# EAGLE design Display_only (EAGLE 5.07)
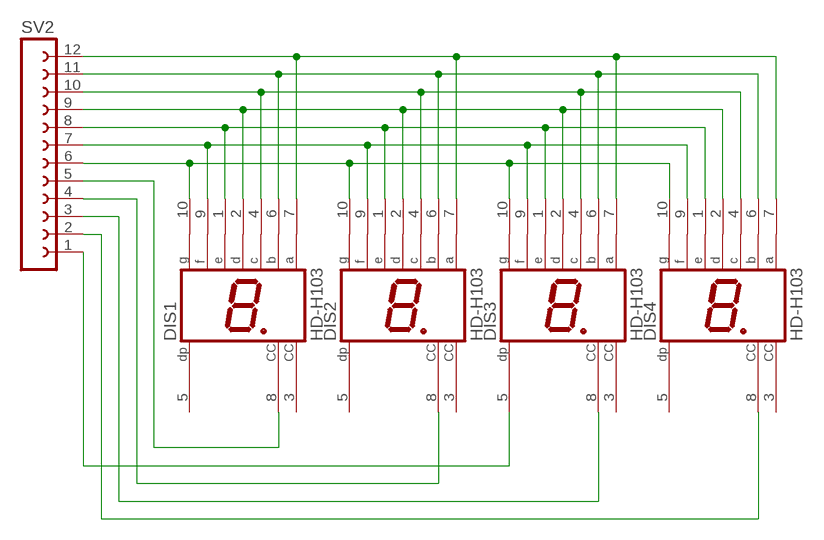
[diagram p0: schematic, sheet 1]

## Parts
DIS1  HD-H103  [HDSP-M]
DIS2  HD-H103  [HDSP-M]
DIS3  HD-H103  [HDSP-M]
DIS4  HD-H103  [HDSP-M]
SV2  FE12-1  [FE12]

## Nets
N$16: DIS1.9(F) DIS2.9(F) DIS3.9(F) DIS4.9(F) SV2.7
N$17: DIS1.7(A) DIS2.7(A) DIS3.7(A) DIS4.7(A) SV2.12
N$18: DIS1.6(B) DIS2.6(B) DIS3.6(B) DIS4.6(B) SV2.11
N$19: DIS1.4(C) DIS2.4(C) DIS3.4(C) DIS4.4(C) SV2.10
N$20: DIS1.2(D) DIS2.2(D) DIS3.2(D) DIS4.2(D) SV2.9
N$21: DIS1.1(E) DIS2.1(E) DIS3.1(E) DIS4.1(E) SV2.8
N$22: DIS1.10(G) DIS2.10(G) DIS3.10(G) DIS4.10(G) SV2.6
N$27: DIS4.8(CC) SV2.2
N$44: DIS3.5(DP) SV2.1
N$53: DIS1.8(CC) SV2.5
N$54: DIS2.8(CC) SV2.4
N$55: DIS3.8(CC) SV2.3
Unconnected: DIS1.3(CC) DIS1.5(DP) DIS2.3(CC) DIS2.5(DP) DIS3.3(CC) DIS4.3(CC) DIS4.5(DP)

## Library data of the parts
DIS1-DIS4 = display-hp:HD-H103: LED DISPLAY 1-character 7 segment, decimal point right
SV2 = con-lsta:FE12-1: FEMALE HEADER

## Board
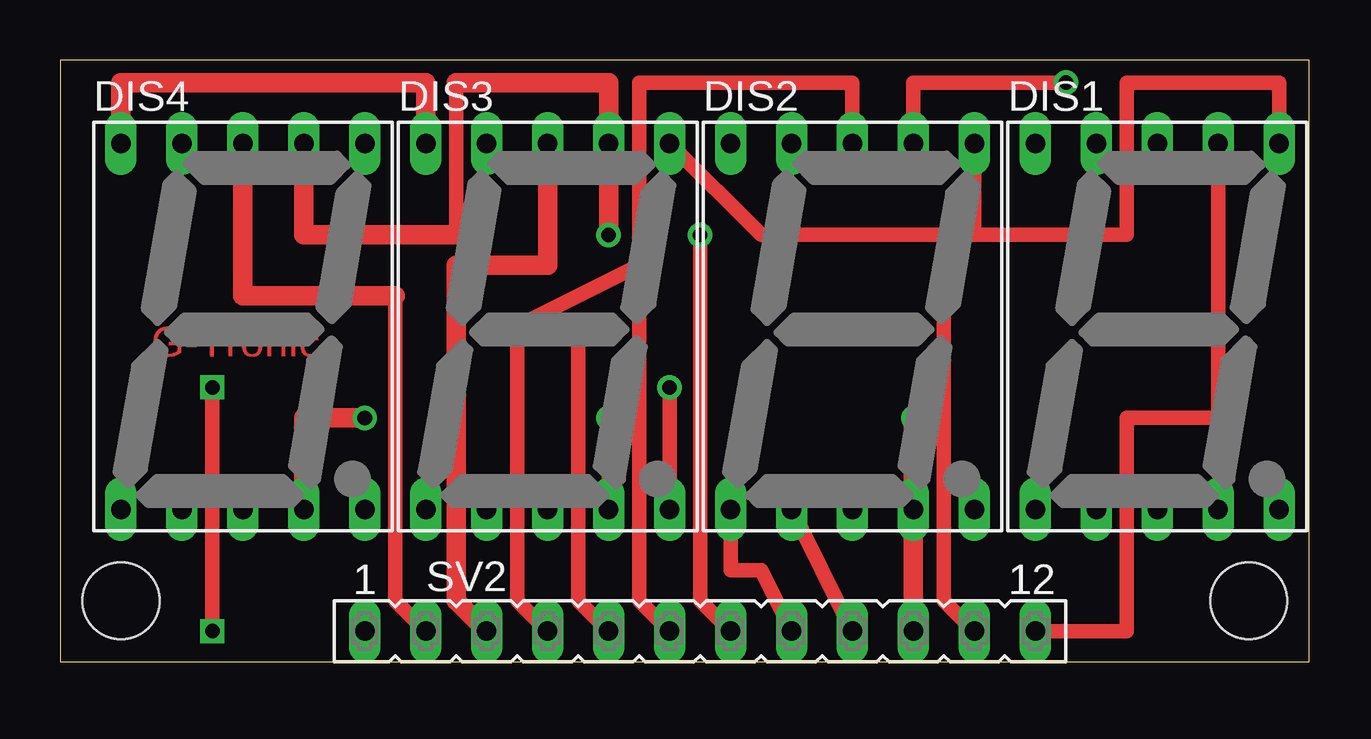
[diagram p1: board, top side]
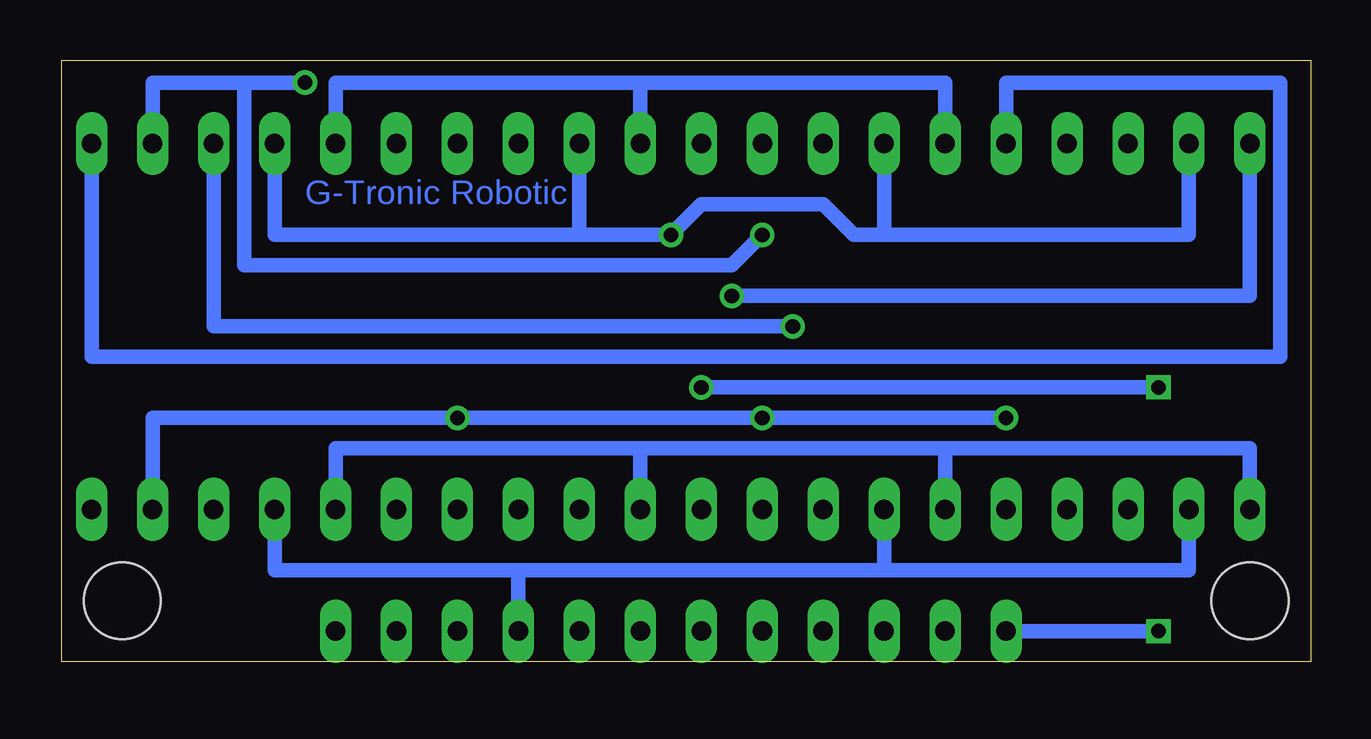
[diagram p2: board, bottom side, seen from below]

Size 52.05 x 25.07 mm. Coordinates in mm from the lower left corner, seen from the top.
Outline: 0,0 52.05,0 52.05,25.07 0,25.07 0,0
Copper layers (1*16): Top 0.035mm / dielectric 1.5mm / Bottom 0.035mm
Design rules "default": minimum track width 10mil, minimum drill 24mil, track to track 8mil, track to pad 8mil, pad to pad 8mil, via to via 8mil, smd to smd 8mil, copper to edge 40mil, drill to drill 8mil, minimum pad ring 10mil, minimum via ring 8mil, stop-mask expansion 4mil, vias tented up to drill 0mil, thermal gap 10mil
Holes 3.2 mm at 49.53,2.54 2.54,2.54

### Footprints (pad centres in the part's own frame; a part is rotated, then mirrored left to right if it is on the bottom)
HDSP-M = drill 0.813 long: 1 -5.08,-7.62; 2 -2.54,-7.62; 3 0,-7.62; 4 2.54,-7.62; 5 5.08,-7.62; 6 5.08,7.62; 7 2.54,7.62; 8 0,7.62; 9 -2.54,7.62; 10 -5.08,7.62
FE12 = drill 0.813 long: 1 -13.97,0; 2 -11.43,0; 3 -8.89,0; 4 -6.35,0; 5 -3.81,0; 6 -1.27,0; 7 1.27,0; 8 3.81,0; 9 6.35,0; 10 8.89,0; 11 11.43,0; 12 13.97,0

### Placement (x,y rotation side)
DIS1  45.72,13.97 0 top
DIS2  33.02,13.97 0 top
DIS3  20.32,13.97 0 top
DIS4  7.62,13.97 0 top
SV2  26.67,1.27 0 top

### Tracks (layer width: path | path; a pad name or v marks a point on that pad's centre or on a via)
N$16  (via drill 0.61)
  Top 0.61: SV2.7 26.67,2.54 v26.67,17.78
  Bottom 0.61: 30.48,17.78 v26.67,17.78 25.4,19.05 20.32,19.05 19.05,17.78 17.78,17.78 | 30.48,17.78 DIS2.9 | DIS4.9 5.08,17.78 17.78,17.78 | 17.78,17.78 DIS3.9 | DIS1.9 43.18,17.78 30.48,17.78
N$17  (via drill 0.61)
  Top 0.61: 16.51,17.78 16.51,24.13 | SV2.12 44.45,1.27 44.45,10.16 48.26,10.16 DIS1.7 | DIS2.7 35.56,24.13 v41.91,24.13
  Top 0.813: DIS4.7 10.16,17.78 16.51,17.78 | 16.51,24.13 22.86,24.13 DIS3.7 v22.86,17.78
  Bottom 0.61: 44.45,24.13 48.26,24.13 DIS1.7 | 44.45,24.13 v41.91,24.13 | v22.86,17.78 24.13,16.51 44.45,16.51 44.45,24.13
N$18
  Top 0.61: SV2.11 36.83,2.54 36.83,17.78 | 38.1,17.78 36.83,17.78 | 36.83,17.78 29.21,17.78 DIS3.6 | 38.1,17.78 DIS2.6 | 38.1,17.78 44.45,17.78 44.45,24.13 50.8,24.13 DIS1.6
  Bottom 0.61: DIS4.6 12.7,24.13 1.27,24.13 1.27,12.7 50.8,12.7 DIS1.6
N$19  (via drill 0.61)
  Top 0.61: v22.86,10.16 DIS3.4
  Top 0.813: SV2.10 DIS2.4 v35.56,10.16 | DIS4.4 10.16,10.16 v12.7,10.16
  Bottom 0.61: v12.7,10.16 v22.86,10.16 v35.56,10.16 48.26,10.16 DIS1.4
N$20
  Top 0.61: SV2.9 DIS2.2
  Bottom 0.61: DIS4.2 5.08,3.81 17.78,3.81 | DIS1.2 43.18,3.81 33.02,3.81 | 33.02,3.81 SV2.9 | 17.78,3.81 DIS3.2 | 17.78,3.81 33.02,3.81
N$21
  Top 0.61: SV2.8 29.21,3.81 27.94,3.81 DIS2.1
  Bottom 0.61: DIS4.1 2.54,8.89 15.24,8.89 | 15.24,8.89 DIS3.1 | DIS1.1 40.64,8.89 27.94,8.89 | 15.24,8.89 27.94,8.89 | 27.94,8.89 DIS2.1
N$22  (via drill 0.61)
  Top 0.61: SV2.6 24.13,2.54 v24.13,15.24
  Top 0.813: DIS4.10 2.54,24.13 15.24,24.13 DIS3.10
  Bottom 0.61: v24.13,15.24 2.54,15.24 DIS4.10 | 27.94,24.13 DIS2.10 | 27.94,24.13 15.24,24.13 DIS3.10 | DIS1.10 40.64,24.13 27.94,24.13
N$27
  Top 0.61: 13.97,15.24 13.97,2.54 SV2.2
  Top 0.813: 13.97,15.24 7.62,15.24 DIS4.8
N$44  (via drill 0.6, 0.61)
  Top 0.61: v6.35,1.27 v6.35,11.43 | v25.4,11.43 DIS3.5
  Bottom 0.61: v6.35,11.43 v25.4,11.43 | v6.35,1.27 SV2.1
N$53  (via drill 0.61)
  Top 0.61: SV2.5 21.59,2.54 v21.59,13.97
  Bottom 0.61: v21.59,13.97 45.72,13.97 DIS1.8
N$54
  Top 0.61: SV2.4 19.05,2.54 19.05,13.97 24.13,16.51 24.13,24.13 33.02,24.13 DIS2.8
N$55
  Top 0.813: SV2.3 16.51,2.54 16.51,16.51 20.32,16.51 DIS3.8

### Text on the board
Top: G-Tronic
Bottom: G-Tronic Robotic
